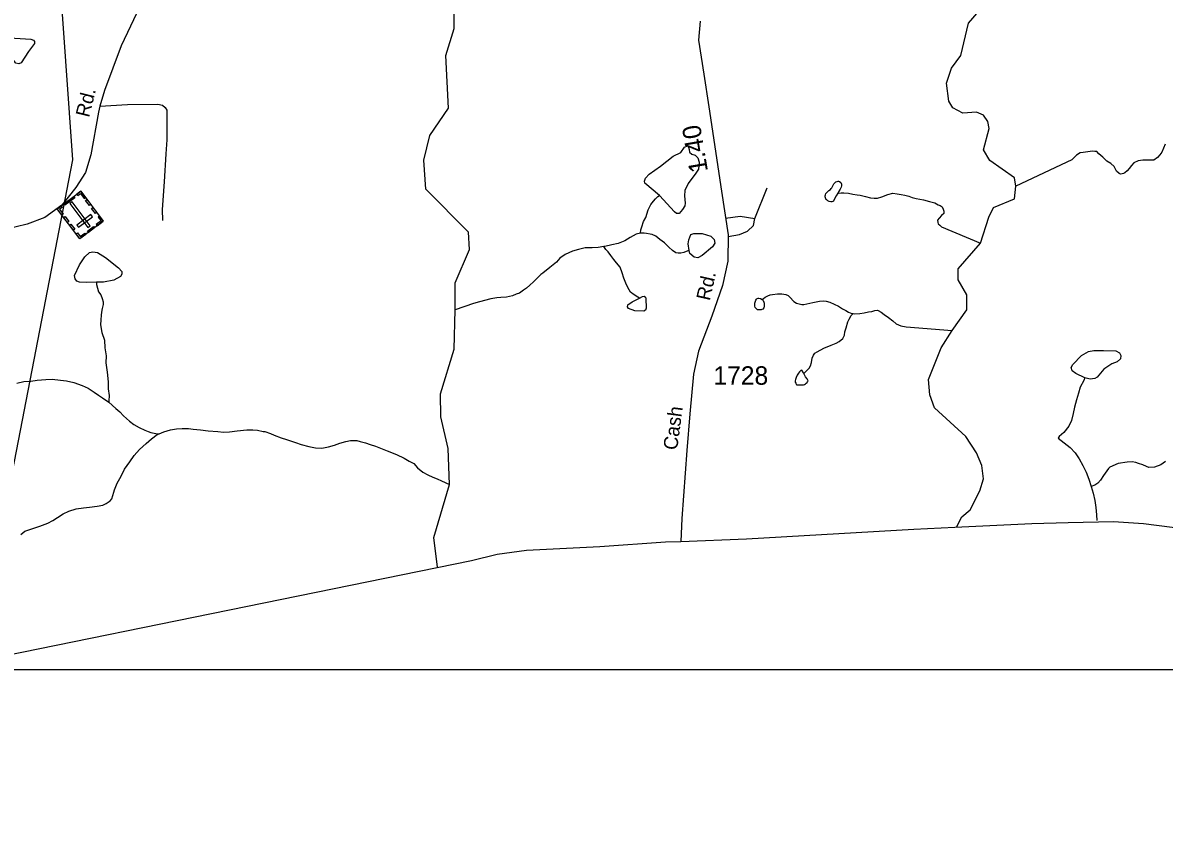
# Model space of a CAD drawing. Extents: x 2056842 to 2160602, y 826753 to 1016856.
# Drawn here: x 2079610 to 2087342, y 844776 to 850234 of the extents above; entities that cross this region are included whole.
import ezdxf

# ---------------------------------------------------------------- set-up
doc = ezdxf.new("R2010")
doc.units = 0
for name, color, linetype in [('Exist Boundary Political CountyLine', 7, 'Continuous'), ('Exist Cultural Cemetery CELL', 7, 'Continuous'), ('Exist Hydrographic Creek Single Shore', 7, 'Continuous'), ('Exist Hydrographic Misc Water Feature', 7, 'Continuous'), ('Exist Road Non-System Type 51', 7, 'Continuous'), ('Exist Road Secondary Mileage Hundredths English Label', 7, 'Continuous'), ('Exist Road Secondary Type 51 Attributed', 7, 'Continuous'), ('Exist Road Secondary Type 51 Label', 7, 'Continuous'), ('Exist Road Secondary Type 51 Number Label', 7, 'Continuous'), ('Exist Utilities Electrical Transmission Line', 7, 'Continuous'), ('Map Preparation Inset Cut Line', 7, 'Continuous')]:
    doc.layers.add(name, color=color, linetype=linetype)

msp = doc.modelspace()

# ---------------------------------------------------------------- linework, layer by layer
at = {"layer": 'Exist Boundary Political CountyLine'}
msp.add_lwpolyline([(2073509.7, 844776), (2076405.2, 845344.1), (2077840.3, 845610.4), (2082649, 846590.6), (2082822.7, 846633.8), (2083021.9, 846660.5), (2083519, 846685.3), (2083962.9, 846716.3), (2084067.4, 846718.6), (2084513.2, 846737), (2085645.1, 846803.3), (2085924.5, 846816.8), (2086446.3, 846841.6), (2086692.1, 846847.3), (2086999.1, 846855.2), (2087202.4, 846841.6), (2088278.5, 846703.3)], dxfattribs=at)
at = {"layer": 'Exist Cultural Cemetery CELL'}
for points in [[(2080155.7, 848888.8), (2079996.8, 848769), (2079843.5, 848972.3), (2080002.5, 849092.2)], [(2079976.1, 849072.2), (2079983, 849063), (2080000.6, 849076.3), (2080024.9, 849044), (2080033.8, 849050.7), (2080002.5, 849092.2)], [(2079963.5, 849048.4), (2079895.7, 848997.3), (2079888.9, 849006.4), (2079956.6, 849057.5)], [(2080051.1, 848846.6), (2080066, 848857.8), (2079943.9, 849019.8), (2079929, 849008.5)], [(2080044.6, 849036.3), (2080070.7, 849001.7), (2080061.6, 848994.9), (2080035.5, 849029.5)], [(2079870, 848992.3), (2079876.9, 848983.1), (2079859.3, 848969.8), (2079883.6, 848937.6), (2079874.7, 848930.9), (2079843.5, 848972.3)], [(2080082.2, 848918.6), (2080071, 848933.5), (2079976.9, 848862.6), (2079988.2, 848847.7)], [(2080085.1, 848982.7), (2080111.1, 848948.1), (2080102, 848941.2), (2080076, 848975.8)], [(2079896.1, 848921.4), (2079922.2, 848886.9), (2079913.1, 848880), (2079887, 848914.6)], [(2079935.7, 848868.8), (2079961.8, 848834.2), (2079952.7, 848827.4), (2079926.7, 848861.9)], [(2080096.6, 848844.3), (2080055.2, 848813.1), (2080048.4, 848822.2), (2080089.7, 848853.4)], [(2080129.7, 848923.4), (2080120.6, 848916.6), (2080140, 848890.9), (2080107.6, 848866.5), (2080114.3, 848857.6), (2080155.7, 848888.8)], [(2079970.6, 848803.6), (2079979.7, 848810.4), (2079999.1, 848784.7), (2080031.4, 848809.1), (2080038.1, 848800.2), (2079996.7, 848769)]]:
    msp.add_lwpolyline(points, close=True, dxfattribs=at)
at = {"layer": 'Exist Hydrographic Creek Single Shore'}
for points in [[(2086336.3, 849126), (2086327.3, 849182), (2086160.2, 849300.3), (2086118.2, 849373.4), (2086157.3, 849518.1), (2086146.7, 849565.6), (2086117.8, 849607.7), (2086070.3, 849628.8), (2085978.1, 849620.9), (2085909.2, 849656.5), (2085883.2, 849702.7), (2085867.4, 849823.9), (2085901.7, 849926.8), (2085964.9, 850011.1), (2086016.2, 850231.8), (2086263.5, 850517.9)], [(2082539.2, 848288.7), (2082538.4, 848472.5), (2082637.2, 848696.8), (2082629.2, 848815.2), (2082340.5, 849106.3), (2082327.4, 849303.7), (2082368.4, 849470.2), (2082493.3, 849654.7), (2082475.2, 850012.7), (2082533.2, 850195.2), (2082532.2, 850329.7)], [(2087349.6, 849410.3), (2087326, 849357.9), (2087312.1, 849338.1), (2087297.5, 849320), (2087272.1, 849301.9), (2087198.1, 849301.8), (2087165.9, 849297.7), (2087136, 849283.6), (2087120.2, 849267.3), (2087104.2, 849245.5), (2087092.1, 849229.4), (2087076.5, 849217.2), (2087066, 849213.5), (2087056.4, 849209.3), (2087046.4, 849207.1), (2087036.3, 849213.1), (2087020.1, 849228.9), (2087002.3, 849259.2), (2086979.9, 849280.9), (2086953.9, 849297), (2086925.8, 849322.8), (2086899.7, 849344.6), (2086885.8, 849360.5), (2086872.1, 849362.6), (2086855.9, 849364.6), (2086823.9, 849358.5), (2086793.7, 849354.5), (2086773.8, 849352.3), (2086747.8, 849336.3), (2086716.2, 849304.3), (2086336.3, 849126)], [(2085934.7, 846816.4), (2085972.3, 846885.8), (2086027.6, 846932.8), (2086093.8, 847061.9), (2086118.8, 847142.9), (2086106.9, 847233.3), (2086070.1, 847320.3), (2085998.9, 847431), (2085785.5, 847625.1), (2085753.9, 847712.1), (2085746, 847817.6), (2085831.3, 848030.7), (2085906.7, 848149), (2086005.2, 848289.6), (2086005.2, 848391.3), (2085946.3, 848491), (2085946.3, 848566.4), (2086098.5, 848741.4), (2086153.2, 848916.5), (2086186.2, 848981.4), (2086327.3, 849040.9), (2086336.3, 849126)], [(2085131, 849079.2), (2085135.3, 849079.3), (2085153.1, 849081.5), (2085173, 849081.3), (2085202.9, 849079.6), (2085232.9, 849073.4), (2085263, 849067.7), (2085283.1, 849065.8), (2085319.2, 849055.9), (2085353, 849047.9), (2085377, 849045.9), (2085399.2, 849046.2), (2085428.9, 849054.2), (2085470.7, 849070.2), (2085503.1, 849078.3), (2085533.1, 849074.6), (2085561, 849070.7), (2085584.9, 849066.7), (2085611.2, 849058.7), (2085635, 849050.7), (2085662.9, 849042.8), (2085712.7, 849033.2), (2085753.1, 849023), (2085789.4, 849013.4), (2085811.1, 849001.2), (2085825.1, 848995.4), (2085837, 848985.5), (2085845.4, 848969.7), (2085849.3, 848957.7), (2085849.3, 848941.5), (2085833.3, 848927.6), (2085817.5, 848909.3), (2085807.4, 848895.4), (2085809.5, 848879.3), (2085811.5, 848871.3), (2085821.4, 848861.3), (2085833.7, 848851.3), (2086098.5, 848741.4)], [(2082419.1, 846544.7), (2082394.2, 846746.3), (2082501.3, 847105), (2082492.2, 847348), (2082441.4, 847562.4), (2082440.4, 847719.8), (2082531.2, 848023.1), (2082539.2, 848288.7)], [(2085235.7, 848263.6), (2085245.6, 848261.7), (2085279.4, 848263.8), (2085309.4, 848267.8), (2085339.5, 848274.2), (2085361.2, 848278.2), (2085381.3, 848284.1), (2085397.5, 848286.1), (2085405.3, 848284.1), (2085425.4, 848272.1), (2085445.7, 848256.4), (2085475.4, 848236.5), (2085503.7, 848214.4), (2085525.9, 848194.4), (2085557.5, 848180.7), (2085593.6, 848172.8), (2085906.7, 848149)]]:
    msp.add_lwpolyline(points, dxfattribs=at)
at = {"layer": 'Exist Hydrographic Misc Water Feature'}
for points in [[(2079525.4, 850012.9), (2079459.6, 850103.4), (2079450.4, 850117.9), (2079453, 850129.8), (2079467.5, 850136.4), (2079557.1, 850128.5), (2079663.8, 850121.9), (2079682.3, 850116.6), (2079688.8, 850107.4), (2079688.8, 850094.2), (2079649.3, 850038.8), (2079599.3, 849962.4), (2079583.5, 849955.8), (2079563.7, 849959.7), (2079553.1, 849971.6), (2079525.4, 850012.9)], [(2083923.2, 849063.4), (2083824, 849147.9), (2083821.4, 849159.8), (2083828, 849180.9), (2083854.3, 849208.6), (2083929.4, 849261.3), (2084016.4, 849329.8), (2084067.8, 849354.9), (2084091.5, 849391.8), (2084112.6, 849399.7), (2084120.5, 849390.5), (2084124.4, 849374.7), (2084127, 849356.2), (2084142.9, 849343), (2084165.3, 849336.4), (2084183.7, 849319.3), (2084192.9, 849290.3), (2084187.7, 849241.5), (2084169.2, 849215.2), (2084117.8, 849145.3), (2084094.1, 849097.8), (2084092.8, 849062.2), (2084098.1, 849012.1), (2084094.1, 848992.4), (2084079.6, 848968.6), (2084057.2, 848942.3), (2084037.5, 848941), (2084024.3, 848952.8), (2083923.2, 849063.4)], [(2085131, 849079.2), (2085119.1, 849061.1), (2085107.2, 849035.3), (2085102.9, 849025.4), (2085096.9, 849023), (2085091.2, 849021.1), (2085083, 849021.1), (2085073.1, 849023), (2085063.3, 849026.9), (2085056.9, 849033.1), (2085053, 849035), (2085048.9, 849040.9), (2085046.9, 849046.9), (2085044.8, 849054.9), (2085045, 849060.9), (2085046.9, 849068.7), (2085048.9, 849077), (2085061.2, 849088.9), (2085071.1, 849097.1), (2085082.6, 849105.1), (2085087.1, 849111), (2085090.8, 849115.3), (2085096.9, 849129.3), (2085104.7, 849143.2), (2085112.9, 849151.3), (2085118.7, 849155.3), (2085126.4, 849159.3), (2085132.8, 849161.2), (2085136.5, 849161.1), (2085142.6, 849157.3), (2085150.6, 849151.2), (2085155, 849141.2), (2085156.8, 849129.2), (2085152.9, 849119.2), (2085146.7, 849107.2), (2085134.9, 849087.5), (2085131, 849079.2)], [(2083794.2, 848809.1), (2083796.1, 848831.1), (2083803.7, 848851.1), (2083815.6, 848887), (2083829.7, 848915.3), (2083847.3, 848965.4), (2083863.5, 849003.5), (2083881.6, 849025.5), (2083895.3, 849041.3), (2083912.9, 849055.6), (2083923.2, 849063.4)], [(2083794.2, 848809.1), (2083766.1, 848801.2), (2083724.1, 848778.8), (2083688, 848756.6), (2083644.3, 848738.5), (2083600, 848728.6), (2083552.1, 848718.4), (2083546.1, 848718.5)], [(2084124.1, 848691), (2084114.3, 848687.9), (2084088.1, 848676.1), (2084068.4, 848671.8), (2084050.5, 848672), (2084034.1, 848675.8), (2084012.2, 848690), (2083986.2, 848713.9), (2083956.2, 848741.5), (2083926.3, 848765.5), (2083898, 848787.3), (2083874.2, 848799.4), (2083860, 848801.2), (2083836.1, 848805.2), (2083820.1, 848809.2), (2083794.2, 848809.1)], [(2084124.1, 848691), (2084117.8, 848735.3), (2084121.8, 848763), (2084136.3, 848798.6), (2084156, 848806.5), (2084211.4, 848806.5), (2084270.7, 848788), (2084294.4, 848764.3), (2084297, 848739.3), (2084281.2, 848715.5), (2084212.7, 848656.2), (2084183.7, 848641.8), (2084158.7, 848645.8), (2084129.7, 848670.8), (2084124.1, 848691)], [(2083546.1, 848718.5), (2083508.4, 848710.4), (2083466.3, 848708.3), (2083420.4, 848707.9), (2083374.5, 848697.9), (2083334.5, 848685.6), (2083284.7, 848663.6), (2083248.8, 848639.4), (2083225, 848611.4), (2083181.1, 848575.4), (2083132.9, 848536.8), (2083119.2, 848527.2), (2083069, 848478.8), (2083045.4, 848456.8), (2083021.2, 848436.5), (2083001.3, 848422.5), (2082975.5, 848402.5), (2082953.3, 848394.5), (2082927.7, 848382.5), (2082887.5, 848374.4), (2082847.7, 848371.9), (2082821.5, 848370.2), (2082781.3, 848364.1), (2082703.6, 848343.9), (2082663.8, 848331.7), (2082539.2, 848288.7)], [(2083787.3, 848367.1), (2083775.4, 848375), (2083751.4, 848389.2), (2083727.2, 848409), (2083709.1, 848439), (2083695.4, 848468.6), (2083681, 848502.9), (2083671, 848538.9), (2083656.8, 848576.7), (2083632.4, 848606.8), (2083614.4, 848628.6), (2083594.5, 848656.4), (2083576.5, 848680.6), (2083560.3, 848698.5), (2083546.1, 848718.5)], [(2080109.4, 848475.4), (2080044.2, 848472.7), (2079994.1, 848475.4), (2079977, 848483.3), (2079963.8, 848499.1), (2079961.2, 848520.2), (2079994.1, 848592.7), (2080031, 848648), (2080061.3, 848677), (2080085, 848681), (2080115.3, 848677), (2080169.4, 848642.8), (2080257.6, 848574.2), (2080280, 848547.9), (2080280, 848530.7), (2080272.1, 848513.6), (2080227.3, 848489.9), (2080157.5, 848476.7), (2080109.4, 848475.4)], [(2080109.4, 848475.4), (2080109.8, 848459.6), (2080115.6, 848435.6), (2080123.8, 848411.6), (2080138.1, 848389.6), (2080147.8, 848365.8), (2080153.9, 848341.7), (2080153.9, 848323.8), (2080148.2, 848297.5), (2080144.3, 848273.8), (2080140.2, 848251.7), (2080138.1, 848221.6), (2080136.3, 848187.7), (2080146.3, 848135.9), (2080162.8, 848083.9), (2080166.9, 848031.8), (2080174.9, 847977.8), (2080173.2, 847929.8), (2080181.4, 847866.1), (2080187.8, 847799.8), (2080187.8, 847754), (2080194.1, 847707.9), (2080193.9, 847671.8), (2080191.9, 847662)], [(2084618.9, 848357.8), (2084627.1, 848365.9), (2084639, 848373.8), (2084657.3, 848383.7), (2084673.3, 848389.8), (2084689.3, 848391.8), (2084723.1, 848396), (2084752.8, 848396), (2084779.1, 848392.4), (2084795.5, 848386.3), (2084807, 848374.3), (2084833.4, 848344.4), (2084851.5, 848334.4), (2084869.1, 848328.5), (2084887.2, 848324.5), (2084901.3, 848324.8), (2084961.4, 848338.8), (2085007.3, 848346.9), (2085035.2, 848349.1), (2085053.2, 848347.2), (2085077.2, 848341.1), (2085107.4, 848327.2), (2085135.1, 848313.3), (2085163.2, 848295.6), (2085185.5, 848283.7), (2085203.8, 848273.7), (2085225.5, 848263.5), (2085235.7, 848263.6)], [(2083787.3, 848367.1), (2083808, 848378.9), (2083818.5, 848380.2), (2083827.7, 848374.9), (2083831.7, 848364.4), (2083833, 848299.8), (2083827.7, 848285.3), (2083817.2, 848280), (2083756.6, 848281.3), (2083713.1, 848298.4), (2083706.5, 848309), (2083709.1, 848322.2), (2083738.1, 848341.9), (2083787.3, 848367.1)], [(2084618.9, 848357.8), (2084625.3, 848351.6), (2084629.4, 848341.6), (2084631.2, 848333.7), (2084633.3, 848323.6), (2084633.3, 848313.8), (2084629.2, 848301.9), (2084623.7, 848293.8), (2084617.5, 848289.9), (2084611.6, 848289.6), (2084605.2, 848287.7), (2084595.4, 848287.6), (2084587.8, 848289.6), (2084577.5, 848297.5), (2084571.2, 848305.4), (2084569.5, 848313.4), (2084569.5, 848325.6), (2084569.5, 848333.7), (2084571.2, 848341.5), (2084575.5, 848353.5), (2084579.2, 848361.4), (2084585.5, 848365.7), (2084591.3, 848367.7), (2084597.2, 848367.6), (2084607.3, 848365.7), (2084618.9, 848357.8)], [(2084901.1, 847856.6), (2084906.6, 847862.6), (2084921, 847876.7), (2084936.8, 847892.9), (2084946.6, 847908.9), (2084952.4, 847930.8), (2084956.7, 847961), (2084966.3, 847981), (2084976.4, 847994.9), (2084990.3, 848002.9), (2085036.4, 848029.2), (2085086.1, 848049.3), (2085120.3, 848063.2), (2085140.2, 848073.5), (2085166, 848093.5), (2085176.1, 848117.6), (2085179.8, 848139.3), (2085187.8, 848167.7), (2085199.7, 848207.7), (2085207.6, 848225.6), (2085221.4, 848249.5), (2085235.7, 848263.6)], [(2086805.1, 847828.8), (2086744.6, 847858.2), (2086719.6, 847875.4), (2086713, 847897.8), (2086722.2, 847918.9), (2086782.8, 847978.2), (2086828.9, 848005.9), (2086864.5, 848012.5), (2086931.7, 848013.8), (2087014.7, 848009.8), (2087038.4, 847998), (2087047.6, 847979.5), (2087045, 847955.8), (2087022.6, 847936), (2086987, 847922.8), (2086934.3, 847887.2), (2086888.2, 847833.2), (2086871.1, 847822.6), (2086839.5, 847818.7), (2086805.1, 847828.8)], [(2084901.1, 847856.6), (2084898.6, 847860.6), (2084886.7, 847880.7), (2084881, 847876.7), (2084870.7, 847868.5), (2084864.8, 847858.4), (2084856.8, 847846.6), (2084848.6, 847830.4), (2084844.9, 847816.4), (2084841.2, 847808.4), (2084842.9, 847798.5), (2084847, 847792.6), (2084849.2, 847782.5), (2084853.1, 847780.7), (2084859.1, 847780.6), (2084867.1, 847780.6), (2084887.2, 847780.8), (2084899, 847780.6), (2084904.8, 847782.6), (2084913.2, 847786.6), (2084916.9, 847790.9), (2084922.8, 847796.9), (2084926.9, 847802.8), (2084930.8, 847806.6), (2084922.6, 847820.9), (2084912.6, 847834.5), (2084901.1, 847856.6)], [(2079569.7, 847792), (2079617.7, 847802.2), (2079663.5, 847806.2), (2079707.5, 847812.5), (2079765.6, 847816.7), (2079809.7, 847818.5), (2079865.6, 847812.9), (2079905.4, 847806.9), (2079955.9, 847795.2), (2080012, 847775.3), (2080053.7, 847757.6), (2080093.9, 847731.7), (2080123.8, 847709.7), (2080150.2, 847691.9), (2080191.9, 847662)], [(2086805.1, 847828.8), (2086796.8, 847810.7), (2086772.8, 847764.4), (2086761.1, 847724.3), (2086747.2, 847678.6), (2086735.3, 847628.5), (2086725.4, 847586.5), (2086713.6, 847538.4), (2086695.3, 847500.2), (2086661.5, 847458.3), (2086631.7, 847430.3), (2086623.7, 847419.8)], [(2080191.9, 847662), (2080240.3, 847620.2), (2080266.5, 847596.3), (2080292.1, 847570.1), (2080332.5, 847534.4), (2080362.5, 847512.4), (2080398.4, 847490.7), (2080436.7, 847472.7), (2080460.5, 847463), (2080476.5, 847457), (2080510.7, 847450.9), (2080534.7, 847448.9)], [(2080534.7, 847448.9), (2080564.7, 847461), (2080610.4, 847475.2), (2080650.6, 847483.3), (2080690.4, 847485.4), (2080732.4, 847485.5), (2080764.6, 847479.9), (2080814.6, 847475.9), (2080866.7, 847468), (2080930.7, 847464.4), (2080968.8, 847460.3), (2081010.6, 847462.4), (2081062.3, 847468.8), (2081128.3, 847475), (2081168.3, 847475), (2081200.3, 847473), (2081238.7, 847465.2), (2081250.6, 847463.3), (2081288.7, 847449.5), (2081312.5, 847439.4), (2081360.5, 847421.6), (2081396.8, 847409.6), (2081456.8, 847389.9), (2081494.8, 847376), (2081546.9, 847362), (2081592.8, 847352.3), (2081636.7, 847350.5), (2081681, 847360.8), (2081720.7, 847372.6), (2081756.8, 847385), (2081798.7, 847396.9), (2081830.9, 847403), (2081872.5, 847403.2), (2081894.4, 847397.4), (2081930.7, 847387.5), (2081962.7, 847375.7), (2081999, 847363.7), (2082033, 847351.6), (2082079, 847333.8), (2082140.9, 847308.1), (2082193, 847284.4), (2082227, 847264.2), (2082259, 847246.4), (2082284.8, 847218.5), (2082319.5, 847188.5), (2082353.5, 847170.8), (2082387.4, 847154.7), (2082417.3, 847142.8), (2082445.6, 847128.9), (2082501.3, 847105)], [(2079597, 846766.2), (2079624.9, 846788.4), (2079658.7, 846800.3), (2079725, 846822.7), (2079778.9, 846842.5), (2079812.9, 846860.9), (2079844.7, 846880.8), (2079884.3, 846906.9), (2079922.6, 846925), (2079972.7, 846939.3), (2080022.3, 846947.6), (2080062.1, 846951.7), (2080114.2, 846957.6), (2080152.5, 846966), (2080174.2, 846976.1), (2080202.3, 846994.2), (2080212.2, 847008.1), (2080225.9, 847052.3), (2080232.1, 847068), (2080249.9, 847114), (2080275.7, 847162.4), (2080299.5, 847208.3), (2080335.6, 847258.4), (2080365.1, 847300.6), (2080401, 847342.6), (2080445.1, 847382.6), (2080481, 847414.9), (2080521, 847442.9), (2080534.7, 847448.9)], [(2086623.7, 847419.8), (2086665.4, 847387.5), (2086704.1, 847354.8), (2086739, 847319.1), (2086767.1, 847278.3), (2086791.3, 847234.5), (2086812.4, 847188.3), (2086830.6, 847141.7), (2086847.9, 847092)], [(2087350.2, 847260.5), (2087320.1, 847238.4), (2087276.2, 847222.3), (2087238.5, 847219.9), (2087222.5, 847225.9), (2087196.4, 847238), (2087168.4, 847247.9), (2087150.1, 847253.9), (2087126.1, 847257.6), (2087090.2, 847255.7), (2087030.6, 847247.3), (2086974.4, 847221.3), (2086964.5, 847213.1), (2086952.4, 847197.1), (2086930.5, 847165.1), (2086910.6, 847134.9), (2086892.8, 847114.8), (2086872.7, 847100.9), (2086847.9, 847092)], [(2086847.9, 847092), (2086860.6, 847046.3), (2086871.6, 846997.2), (2086879, 846948.1), (2086883.9, 846898.3), (2086886.1, 846861.6)]]:
    msp.add_lwpolyline(points, dxfattribs=at)
at = {"layer": 'Exist Road Non-System Type 51'}
msp.add_line((2084568.6, 848906.9), (2084653.7, 849114.7), dxfattribs=at)
for points in [[(2080132.8, 849669.4), (2080320.2, 849680.6), (2080524.4, 849682.3), (2080556.3, 849674.5), (2080575.3, 849659), (2080584.8, 849642.6), (2080585.7, 849585.6), (2080584.8, 849440.4), (2080579.6, 849345.4), (2080566.7, 849155.4), (2080554.1, 848968.8), (2080556.3, 848893.6)], [(2084371.4, 848910.6), (2084468.9, 848923.5), (2084568.6, 848906.9)], [(2084389.1, 848784.7), (2084464.7, 848798.8), (2084518.7, 848821.7), (2084560.3, 848859.1), (2084568.6, 848906.9)]]:
    msp.add_lwpolyline(points, dxfattribs=at)
at = {"layer": 'Exist Road Secondary Type 51 Attributed'}
for points in [[(2082612.5, 852919.6), (2082446.6, 852816.4), (2082145.4, 852604.4), (2081989.6, 852481.8), (2081798.6, 852280.2), (2081276.2, 851624.5), (2080789.2, 851012.4), (2080610.6, 850756.8), (2080508.8, 850569.7), (2080277.2, 850078.2), (2080163, 849773.9), (2080132.8, 849669.4), (2080123.5, 849627.1), (2080070.5, 849339.3), (2080035.2, 849218.7), (2079968.8, 849116.9), (2079875.3, 848998.4), (2079759, 848915.3), (2079640.6, 848869.6), (2079491.1, 848832.2), (2079177.5, 848836.3), (2078779.7, 848824.9)], [(2084199.8, 850245.3), (2084187.4, 850116.4), (2084224.2, 849886.3), (2084256.4, 849663.9), (2084343.1, 849091.8), (2084389.3, 848796.1), (2084386.2, 848619.5), (2084350.4, 848452.7), (2084278.7, 848245.9), (2084186.8, 848008.4), (2084153.6, 847852.6), (2084129.2, 847583.9), (2084109.5, 847335.6), (2084075.1, 846874.7), (2084067.4, 846718.6)]]:
    msp.add_lwpolyline(points, dxfattribs=at)
at = {"layer": 'Exist Utilities Electrical Transmission Line'}
msp.add_lwpolyline([(2079289.6, 845905.8), (2079948.4, 849305.4), (2079483.2, 855866.2), (2080101, 858353.8), (2081583.8, 864201.8), (2082616, 868304.1), (2080660.7, 871519), (2079505, 873046.5), (2077150, 875999.6), (2076168.7, 877076.1), (2079417.8, 882691.3), (2077477.1, 888146.6), (2075950.7, 892161.6), (2073748.3, 895216.6), (2070106.7, 900031.7)], dxfattribs=at)
at = {"layer": 'Map Preparation Inset Cut Line'}
msp.add_lwpolyline([(2059276.8, 845851.8), (2104036.2, 845851.8), (2104036.2, 868310.8), (2085975.1, 868308.6), (2085982, 877260.1), (2059276.8, 877260.1), (2059276.8, 845851.8)], dxfattribs=at)

# ---------------------------------------------------------------- texts
at = {"layer": 'Exist Road Secondary Mileage Hundredths English Label'}
msp.add_text('1.40', height=125, rotation=99.63943, dxfattribs=at).set_placement((2084252.1, 849228.7))
at = {"layer": 'Exist Road Secondary Type 51 Label'}
for s, rotation, p in [('Rd.', 76.04558, (2080058.5, 849587.8)), ('Rd.', 77.32356, (2084263.6, 848346)), ('Cash', 82.44501, (2084042.2, 847334.5))]:
    msp.add_text(s, height=95, rotation=rotation, dxfattribs=at).set_placement(p)
at = {"layer": 'Exist Road Secondary Type 51 Number Label'}
msp.add_text('1728', height=125, dxfattribs=at).set_placement((2084288, 847781))

doc.saveas('drawing.dxf')
